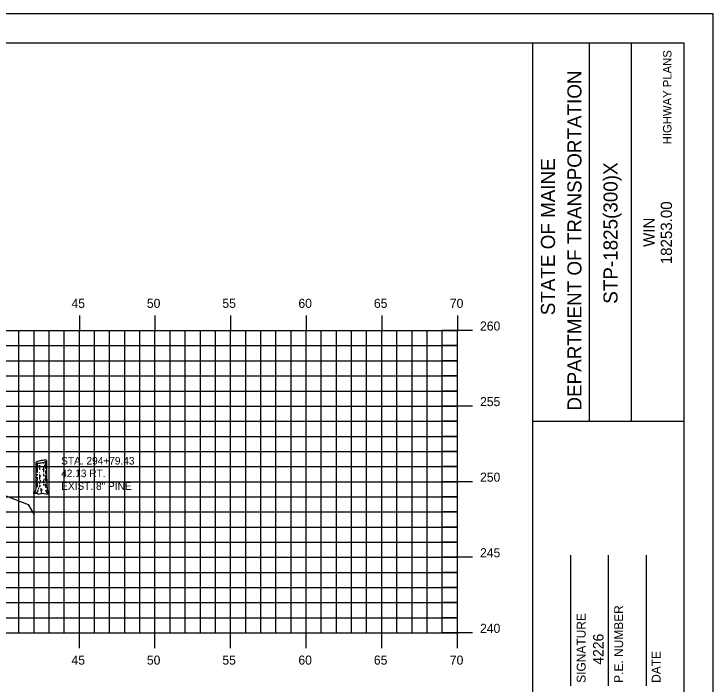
# Model space of a CAD drawing. Extents: x 859352 to 859522, y 366268 to 366378.
# Drawn here: x 859475.8 to 859522.04, y 366333.85 to 366378.18 of the extents above; entities that cross this region are included whole.
import ezdxf

# ---------------------------------------------------------------- set-up
doc = ezdxf.new("R2010")
doc.units = 0
for name, color, linetype in [('ANNOTATION', 7, 'Continuous'), ('BORDER', 7, 'Continuous'), ('D_Text_Monospaced', 7, 'Continuous'), ('H_V ANNOTATION', 7, 'Continuous'), ('HIGHWAY_TITLE', 7, 'Continuous'), ('MAJOR', 7, 'Continuous'), ('MINOR', 7, 'Continuous'), ('PLOT BOUNDARY', 7, 'Continuous'), ('S_Roadway_Centerline', 7, 'Continuous'), ('S_Trees_Conifer_NonPay', 7, 'Continuous')]:
    doc.layers.add(name, color=color, linetype=linetype)

msp = doc.modelspace()

# ---------------------------------------------------------------- linework, layer by layer
at = {"layer": 'BORDER'}
for p, q in [((859520.13, 366376.236), (859360.13, 366376.236)), ((859510.13, 366271.236), (859510.13, 366376.239)), ((859513.858, 366351.234), (859513.858, 366376.234)), ((859516.653, 366351.234), (859516.653, 366376.234)), ((859520.13, 366271.236), (859520.13, 366376.236)), ((859510.131, 366351.231), (859520.13, 366351.231)), ((859512.63, 366333.739), (859512.63, 366342.387)), ((859515.13, 366333.739), (859515.13, 366342.387)), ((859517.63, 366333.739), (859517.63, 366342.387))]:
    msp.add_line(p, q, dxfattribs=at)
at = {"layer": 'MAJOR'}
for p, q in [((859480.129, 366358.238), (859480.129, 366357.236)), ((859485.129, 366358.238), (859485.129, 366357.236)), ((859490.129, 366358.238), (859490.129, 366357.236)), ((859495.129, 366358.238), (859495.129, 366357.236)), ((859500.129, 366358.238), (859500.129, 366357.236)), ((859505.129, 366358.238), (859505.129, 366357.236)), ((859365.129, 366357.236), (859505.129, 366357.236)), ((859365.129, 366357.236), (859505.129, 366357.236)), ((859480.129, 366337.236), (859480.129, 366357.236)), ((859485.129, 366337.236), (859485.129, 366357.236)), ((859490.129, 366337.236), (859490.129, 366357.236)), ((859495.129, 366337.236), (859495.129, 366357.236)), ((859500.129, 366337.236), (859500.129, 366357.236)), ((859506.131, 366357.236), (859504.127, 366357.236)), ((859505.129, 366337.236), (859505.129, 366357.236)), ((859505.129, 366337.236), (859505.129, 366357.236)), ((859365.129, 366352.236), (859505.129, 366352.236)), ((859506.131, 366352.236), (859504.127, 366352.236)), ((859365.129, 366347.236), (859505.129, 366347.236)), ((859506.131, 366347.236), (859504.127, 366347.236)), ((859365.129, 366342.236), (859505.129, 366342.236)), ((859506.131, 366342.236), (859504.127, 366342.236)), ((859365.129, 366337.236), (859505.129, 366337.236)), ((859365.129, 366337.236), (859505.129, 366337.236)), ((859480.129, 366336.234), (859480.129, 366337.236)), ((859485.129, 366336.234), (859485.129, 366337.236)), ((859490.129, 366336.234), (859490.129, 366337.236)), ((859495.129, 366336.234), (859495.129, 366337.236)), ((859500.129, 366336.234), (859500.129, 366337.236)), ((859506.131, 366337.236), (859504.127, 366337.236)), ((859505.129, 366336.234), (859505.129, 366337.236))]:
    msp.add_line(p, q, dxfattribs=at)
at = {"layer": 'MINOR'}
for p, q in [((859476.129, 366337.236), (859476.129, 366357.236)), ((859477.129, 366337.236), (859477.129, 366357.236)), ((859478.129, 366337.236), (859478.129, 366357.236)), ((859479.129, 366337.236), (859479.129, 366357.236)), ((859481.129, 366337.236), (859481.129, 366357.236)), ((859482.129, 366337.236), (859482.129, 366357.236)), ((859483.129, 366337.236), (859483.129, 366357.236)), ((859484.129, 366337.236), (859484.129, 366357.236)), ((859486.129, 366337.236), (859486.129, 366357.236)), ((859487.129, 366337.236), (859487.129, 366357.236)), ((859488.129, 366337.236), (859488.129, 366357.236)), ((859489.129, 366337.236), (859489.129, 366357.236)), ((859491.129, 366337.236), (859491.129, 366357.236)), ((859492.129, 366337.236), (859492.129, 366357.236)), ((859493.129, 366337.236), (859493.129, 366357.236)), ((859494.129, 366337.236), (859494.129, 366357.236)), ((859496.129, 366337.236), (859496.129, 366357.236)), ((859497.129, 366337.236), (859497.129, 366357.236)), ((859498.129, 366337.236), (859498.129, 366357.236)), ((859499.129, 366337.236), (859499.129, 366357.236)), ((859501.129, 366337.236), (859501.129, 366357.236)), ((859502.129, 366337.236), (859502.129, 366357.236)), ((859503.129, 366337.236), (859503.129, 366357.236)), ((859504.129, 366337.236), (859504.129, 366357.236)), ((859365.129, 366356.236), (859505.129, 366356.236)), ((859505.129, 366356.236), (859504.127, 366356.236)), ((859365.129, 366355.236), (859505.129, 366355.236)), ((859505.129, 366355.236), (859504.127, 366355.236)), ((859365.129, 366354.236), (859505.129, 366354.236)), ((859505.129, 366354.236), (859504.127, 366354.236)), ((859365.129, 366353.236), (859505.129, 366353.236)), ((859505.129, 366353.236), (859504.127, 366353.236)), ((859365.129, 366351.236), (859505.129, 366351.236)), ((859505.129, 366351.236), (859504.127, 366351.236)), ((859365.129, 366350.236), (859505.129, 366350.236)), ((859505.129, 366350.236), (859504.127, 366350.236)), ((859365.129, 366349.236), (859505.129, 366349.236)), ((859505.129, 366349.236), (859504.127, 366349.236)), ((859365.129, 366348.236), (859505.129, 366348.236)), ((859505.129, 366348.236), (859504.127, 366348.236)), ((859365.129, 366346.236), (859505.129, 366346.236)), ((859505.129, 366346.236), (859504.127, 366346.236)), ((859365.129, 366345.236), (859505.129, 366345.236)), ((859505.129, 366345.236), (859504.127, 366345.236)), ((859365.129, 366344.236), (859505.129, 366344.236)), ((859505.129, 366344.236), (859504.127, 366344.236)), ((859365.129, 366343.236), (859505.129, 366343.236)), ((859505.129, 366343.236), (859504.127, 366343.236)), ((859365.129, 366341.236), (859505.129, 366341.236)), ((859505.129, 366341.236), (859504.127, 366341.236)), ((859365.129, 366340.236), (859505.129, 366340.236)), ((859505.129, 366340.236), (859504.127, 366340.236)), ((859365.129, 366339.236), (859505.129, 366339.236)), ((859365.129, 366339.236), (859505.129, 366339.236)), ((859505.129, 366339.236), (859504.127, 366339.236)), ((859365.129, 366338.236), (859505.129, 366338.236)), ((859505.129, 366338.236), (859504.127, 366338.236))]:
    msp.add_line(p, q, dxfattribs=at)
at = {"layer": 'PLOT BOUNDARY'}
msp.add_lwpolyline([(859352.036, 366268.177), (859522.036, 366268.177), (859522.036, 366378.177), (859352.036, 366378.177)], close=True, dxfattribs=at)
at = {"layer": 'S_Roadway_Centerline'}
msp.add_lwpolyline([(859475.033, 366346.391), (859476.741, 366345.729), (859477.149, 366345.05)], dxfattribs=at)
at = {"layer": 'S_Trees_Conifer_NonPay'}
for p, q in [((859477.336, 366348.462), (859477.336, 366348.257)), ((859477.755, 366348.518), (859477.755, 366348.439)), ((859477.336, 366348.184), (859477.336, 366347.853)), ((859477.493, 366348.338), (859477.493, 366348.064)), ((859477.755, 366348.189), (859477.755, 366347.864)), ((859477.889, 366348.229), (859477.889, 366348.098)), ((859477.889, 366347.989), (859477.889, 366347.763)), ((859477.336, 366347.739), (859477.336, 366347.66)), ((859477.336, 366347.546), (859477.336, 366347.436)), ((859477.493, 366347.71), (859477.493, 366347.392)), ((859477.755, 366347.763), (859477.755, 366347.609)), ((859477.889, 366347.671), (859477.889, 366347.295)), ((859477.319, 366347.359), (859477.319, 366347.262)), ((859477.336, 366347.147), (859477.336, 366346.88)), ((859477.493, 366347.222), (859477.493, 366347.063)), ((859477.493, 366347.005), (859477.493, 366346.874)), ((859477.534, 366347.348), (859477.534, 366347.278)), ((859477.755, 366347.381), (859477.755, 366347.147)), ((859477.755, 366347.085), (859477.755, 366346.999)), ((859477.871, 366347.102), (859477.888, 366346.857)), ((859477.95, 366346.874), (859478.01, 366346.88))]:
    msp.add_line(p, q, dxfattribs=at)
for points in [[(859477.257, 366348.497), (859477.257, 366346.779), (859477.188, 366346.522), (859477.068, 366346.488), (859477.285, 366346.472), (859477.444, 366346.413), (859477.654, 366346.472), (859477.916, 366346.424), (859478.122, 366346.43), (859477.971, 366346.533), (859477.899, 366346.687)], [(859477.889, 366348.558), (859477.889, 366348.461), (859477.889, 366348.296)], [(859478, 366346.513), (859478.116, 366346.522), (859478.024, 366346.647), (859477.991, 366347.188), (859477.971, 366347.705), (859477.971, 366348.624)], [(859477.285, 366346.472), (859477.375, 366346.584), (859477.392, 366346.698)], [(859477.416, 366346.834), (859477.405, 366346.79), (859477.456, 366346.779), (859477.456, 366346.84)], [(859477.654, 366346.472), (859477.609, 366346.647), (859477.603, 366346.812)], [(859477.607, 366346.697), (859477.677, 366346.692), (859477.695, 366346.745)]]:
    msp.add_lwpolyline(points, dxfattribs=at)
for centre, radius, start, end in [((859477.276, 366348.496), 0.0186, 160.3798, 174.3267), ((859477.271, 366348.497), 0.0141, 174.3267, 190.3798), ((859477.283, 366348.494), 0.0263, 141.6195, 160.3798), ((859477.271, 366348.497), 0.0141, 190.3798, 206.433), ((859477.272, 366348.381), 0.0143, 180, 196.0515), ((859477.275, 366348.499), 0.0186, 206.433, 220.3798), ((859477.281, 366348.504), 0.0263, 220.3798, 239.1402), ((859477.32, 366348.465), 0.0729, 130.3798, 141.6195), ((859477.305, 366348.544), 0.0729, 239.1402, 250.3798), ((859477.431, 366348.333), 0.245, 108.3946, 130.3798), ((859477.363, 366348.706), 0.245, 250.3798, 272.3651), ((859477.93, 366346.834), 1.825, 100.3798, 108.3946), ((859477.298, 366350.285), 1.825, 272.3651, 280.3798), ((859477.93, 366346.834), 1.825, 92.3651, 100.3798), ((859477.298, 366350.285), 1.825, 280.3798, 288.3946), ((859477.865, 366348.413), 0.245, 70.3798, 92.3651), ((859477.796, 366348.785), 0.245, 288.3946, 310.3798), ((859477.923, 366348.575), 0.0729, 59.1402, 70.3798), ((859477.908, 366348.654), 0.0729, 310.3798, 321.6195), ((859477.946, 366348.615), 0.0263, 40.3798, 59.1402), ((859477.945, 366348.386), 0.0267, 311.2506, 330), ((859477.945, 366348.625), 0.0263, 321.6195, 340.3798), ((859477.952, 366348.62), 0.0186, 26.433, 40.3798), ((859477.956, 366348.622), 0.0141, 10.3798, 26.433), ((859477.952, 366348.623), 0.0186, 340.3798, 354.3267), ((859477.952, 366348.382), 0.0189, 330, 343.9485), ((859477.956, 366348.622), 0.0141, 354.3267, 10.3798), ((859477.272, 366347.915), 0.0143, 180, 196.0515), ((859477.277, 366347.916), 0.0189, 196.0515, 210), ((859477.402, 366348.317), 0.245, 244.3148, 257.5375), ((859477.4, 366348.569), 0.245, 254.8461, 261.8968), ((859477.614, 366350.077), 1.767, 261.8968, 262.605), ((859477.614, 366350.077), 1.767, 264.3267, 266.0499), ((859477.616, 366349.825), 1.767, 265.8991, 267.5962), ((859477.616, 366349.825), 1.767, 272.7221, 274.4847), ((859477.614, 366350.077), 1.767, 276.2449, 278.1032), ((859477.829, 366348.569), 0.245, 278.1032, 284.1859), ((859477.829, 366348.569), 0.245, 291.7653, 300), ((859477.914, 366348.421), 0.0738, 300, 311.2506), ((859477.947, 366348.134), 0.0267, 311.2506, 330), ((859477.952, 366347.916), 0.0189, 330, 343.9485), ((859477.954, 366348.13), 0.0189, 330, 343.9485), ((859477.272, 366347.703), 0.0143, 180, 196.0515), ((859477.277, 366347.705), 0.0189, 196.0515, 210), ((859477.283, 366347.92), 0.0267, 210, 228.7494), ((859477.284, 366347.709), 0.0267, 210, 228.7494), ((859477.314, 366347.955), 0.0738, 228.7494, 240), ((859477.315, 366347.744), 0.0738, 228.7494, 240), ((859477.4, 366348.103), 0.245, 240, 246.7914), ((859477.4, 366347.892), 0.245, 240, 254.9514), ((859477.4, 366348.103), 0.245, 254.8461, 257.5454), ((859477.614, 366349.611), 1.767, 265.2285, 266.1325), ((859477.615, 366349.399), 1.767, 266.0429, 268.5525), ((859477.615, 366349.399), 1.767, 274.5361, 277.0026), ((859477.829, 366348.103), 0.245, 284.1859, 300), ((859477.829, 366347.892), 0.245, 292.1924, 300), ((859477.914, 366347.955), 0.0738, 300, 311.2506), ((859477.915, 366347.744), 0.0738, 300, 311.2506), ((859477.945, 366347.92), 0.0267, 311.2506, 330), ((859477.946, 366347.709), 0.0267, 311.2506, 330), ((859477.952, 366347.705), 0.0189, 330, 343.9485), ((859477.272, 366347.267), 0.0143, 180, 196.0515), ((859477.271, 366347.061), 0.0143, 180, 196.0515), ((859477.275, 366347.063), 0.0189, 196.0515, 210), ((859477.282, 366347.066), 0.0267, 210, 228.7494), ((859477.313, 366347.102), 0.0738, 228.7494, 240), ((859477.399, 366347.25), 0.245, 240, 249.1675), ((859477.399, 366347.673), 0.245, 254.9814, 261.8968), ((859477.614, 366349.18), 1.767, 261.8968, 262.45), ((859477.614, 366348.963), 1.767, 262.2622, 265.0496), ((859477.613, 366348.757), 1.767, 266.0862, 268.2187), ((859477.614, 366348.963), 1.767, 272.6293, 274.5612), ((859477.613, 366348.757), 1.767, 274.2776, 276.3006), ((859477.614, 366349.18), 1.767, 276.7966, 278.1032), ((859477.614, 366348.963), 1.767, 277.63, 278.1032), ((859477.828, 366347.673), 0.245, 278.1032, 284.3207), ((859477.828, 366347.455), 0.245, 278.1032, 294.6056), ((859477.828, 366347.25), 0.245, 284.0684, 300), ((859477.913, 366347.102), 0.0738, 300, 302.05)]:
    msp.add_arc(centre, radius, start, end, dxfattribs=at)

# ---------------------------------------------------------------- texts
at = {"layer": 'ANNOTATION'}
msp.add_text('4226', height=0.69, rotation=90, dxfattribs=at).set_placement((859514.794, 366335.13))
at = {"layer": 'BORDER'}
for s, height, p in [('DEPARTMENT OF TRANSPORTATION', 0.93176, (859513.336, 366351.942)), ('STATE OF MAINE', 0.93176, (859511.585, 366358.248)), ('STP-1825(300)X', 0.93176, (859515.722, 366359.008)), ('18253.00', 0.7453, (859519.325, 366361.623)), ('WIN', 0.7453, (859518.166, 366362.766)), ('P.E. NUMBER', 0.59055, (859516.09, 366333.932)), ('SIGNATURE', 0.5906, (859513.61, 366333.932)), ('DATE', 0.5906, (859518.571, 366333.932))]:
    msp.add_text(s, height=height, rotation=90, dxfattribs=at).set_placement(p)
at = {"layer": 'D_Text_Monospaced'}
for s, height, p in [('STA. 294+79.43', 0.49998, (859478.924, 366348.373)), ('42.13 RT.', 0.5, (859478.924, 366347.539)), ('EXIST. 8" PINE', 0.49998, (859478.924, 366346.699))]:
    msp.add_text(s, height=height, dxfattribs=at).set_placement(p)
at = {"layer": 'H_V ANNOTATION'}
for s, p in [('45', (859479.608, 366358.736)), ('50', (859484.594, 366358.736)), ('55', (859489.586, 366358.736)), ('60', (859494.616, 366358.736)), ('65', (859499.608, 366358.736)), ('70', (859504.631, 366358.736)), ('260', (859506.629, 366357.236)), ('255', (859506.629, 366352.236)), ('250', (859506.629, 366347.236)), ('245', (859506.629, 366342.236)), ('240', (859506.629, 366337.236)), ('45', (859479.608, 366335.136)), ('50', (859484.594, 366335.136)), ('55', (859489.586, 366335.136)), ('60', (859494.616, 366335.136)), ('65', (859499.608, 366335.136)), ('70', (859504.631, 366335.136))]:
    msp.add_text(s, height=0.6, dxfattribs=at).set_placement(p)
at = {"layer": 'HIGHWAY_TITLE'}
msp.add_text('HIGHWAY PLANS', height=0.55901, rotation=90, dxfattribs=at).set_placement((859519.288, 366369.552))

doc.saveas('drawing.dxf')
